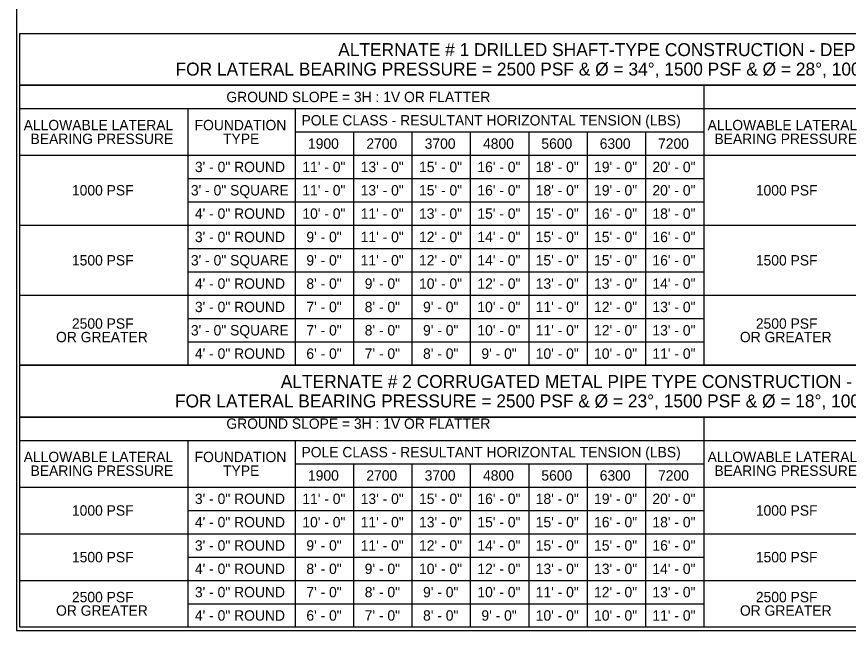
# Model space of a CAD drawing. Extents: x 99862 to 103151, y 100000 to 102076.
# Drawn here: x 99862 to 101145, y 100000 to 100946 of the extents above; entities that cross this region are included whole.
import ezdxf

# ---------------------------------------------------------------- set-up
doc = ezdxf.new("R2010")
doc.units = 0
for name, color, linetype in [('Level 1', 7, 'Continuous'), ('Level 20', 7, 'Continuous'), ('Level 40', 7, 'Continuous'), ('Level 60', 7, 'Continuous')]:
    doc.layers.add(name, color=color, linetype=linetype)

msp = doc.modelspace()

# ---------------------------------------------------------------- linework, layer by layer
at = {"layer": 'Level 1'}
msp.add_lwpolyline([(99862, 99999.5), (103151, 99999.5), (103151, 102075.5), (99862, 102075.5)], close=True, dxfattribs=at)
at = {"layer": 'Level 40'}
for p, q in [((100921.8, 100840.5), (100921.8, 100408.5)), ((99867, 100804.5), (101987.9, 100804.5)), ((100126, 100804.5), (100126, 100408.5)), ((100291.8, 100804.5), (100291.8, 100408.5)), ((100291.8, 100768.5), (100921.8, 100768.5)), ((100381.8, 100768.5), (100381.8, 100408.5)), ((100471.8, 100768.5), (100471.8, 100408.5)), ((100561.8, 100768.5), (100561.8, 100408.5)), ((100651.8, 100768.5), (100651.8, 100408.5)), ((100741.8, 100768.5), (100741.8, 100408.5)), ((100831.8, 100768.5), (100831.8, 100408.5)), ((99867, 100732.5), (101987.9, 100732.5)), ((100126, 100696.5), (100921.8, 100696.5)), ((100126, 100660.5), (100921.8, 100660.5)), ((99867, 100624.5), (101987.9, 100624.5)), ((100126, 100588.5), (100921.8, 100588.5)), ((100126, 100552.5), (100921.8, 100552.5)), ((99867, 100516.5), (101987.9, 100516.5)), ((100126, 100480.5), (100921.8, 100480.5)), ((100126, 100444.5), (100921.8, 100444.5)), ((100921.8, 100328.5), (100921.8, 100004.5)), ((99867, 100292.5), (101987.9, 100292.5)), ((100126, 100292.5), (100126, 100004.5)), ((100291.8, 100292.5), (100291.8, 100004.5)), ((100291.8, 100256.5), (100921.8, 100256.5)), ((100381.8, 100256.5), (100381.8, 100004.5)), ((100471.8, 100256.5), (100471.8, 100004.5)), ((100561.8, 100256.5), (100561.8, 100004.5)), ((100651.8, 100256.5), (100651.8, 100004.5)), ((100741.8, 100256.5), (100741.8, 100004.5)), ((100831.8, 100256.5), (100831.8, 100004.5)), ((99867, 100220.5), (101987.9, 100220.5)), ((100126, 100184.5), (100921.8, 100184.5)), ((99867, 100148.5), (101987.9, 100148.5)), ((100126, 100112.5), (100921.8, 100112.5)), ((99867, 100076.5), (101987.9, 100076.5)), ((100126, 100040.5), (100921.8, 100040.5))]:
    msp.add_line(p, q, dxfattribs=at)
for points in [[(99867, 100920.5), (101987.9, 100920.5), (101987.9, 100840.5), (99867, 100840.5)], [(99867, 100840.5), (101987.9, 100840.5), (101987.9, 100408.5), (99867, 100408.5)], [(99867, 100408.5), (101987.9, 100408.5), (101987.9, 100328.5), (99867, 100328.5)], [(99867, 100328.5), (101987.9, 100328.5), (101987.9, 100004.5), (99867, 100004.5)]]:
    msp.add_lwpolyline(points, close=True, dxfattribs=at)
at = {"layer": 'Level 60'}
msp.add_line((99862, 99999.5), (99862, 99999.5), dxfattribs=at)
msp.add_line((99862, 99999.5), (99862, 99999.5), dxfattribs=at)
msp.add_line((99862, 99999.5), (99862, 99999.5), dxfattribs=at)

# ---------------------------------------------------------------- texts
at = {"layer": 'Level 20'}
for s, height, p in [('ALTERNATE # 1 DRILLED SHAFT-TYPE CONSTRUCTION - DEPTH "D"', 20, (100358, 100885.5)), ('FOR LATERAL BEARING PRESSURE = 2500 PSF & Ø = 34°, 1500 PSF & Ø = 28°, 1000 PSF & Ø = 26°', 20, (100107.1, 100855.5)), ('GROUND SLOPE = 3H : 1V OR FLATTER', 16, (100185.5, 100814.5)), ('ALLOWABLE LATERAL', 16, (99872.9, 100771.1)), ('FOUNDATION', 16, (100136.5, 100771.1)), ('POLE CLASS - RESULTANT HORIZONTAL TENSION (LBS)', 16, (100301.4, 100778.5)), ('ALLOWABLE LATERAL', 16, (100927.8, 100771.1)), ('BEARING PRESSURE', 16, (99883.5, 100749.9)), ('TYPE', 16, (100180.4, 100749.9)), ('BEARING PRESSURE', 16, (100938.3, 100749.9)), ('1900', 16, (100311.4, 100742.5)), ('2700', 16, (100401.4, 100742.5)), ('3700', 16, (100491.4, 100742.5)), ('4800', 16, (100581.4, 100742.5)), ('5600', 16, (100671.4, 100742.5)), ('6300', 16, (100761.4, 100742.5)), ('7200', 16, (100851.4, 100742.5)), ('3\' - 0" ROUND', 16, (100137, 100706.5)), ('11\' - 0"', 16, (100302.7, 100706.5)), ('13\' - 0"', 16, (100392.7, 100706.5)), ('15\' - 0"', 16, (100482.7, 100706.5)), ('16\' - 0"', 16, (100572.7, 100706.5)), ('18\' - 0"', 16, (100662.7, 100706.5)), ('19\' - 0"', 16, (100752.7, 100706.5)), ('20\' - 0"', 16, (100842.7, 100706.5)), ('1000 PSF', 16, (99947.3, 100670.5)), ('3\' - 0" SQUARE', 16, (100130.8, 100670.5)), ('11\' - 0"', 16, (100302.7, 100670.5)), ('13\' - 0"', 16, (100392.7, 100670.5)), ('15\' - 0"', 16, (100482.7, 100670.5)), ('16\' - 0"', 16, (100572.7, 100670.5)), ('18\' - 0"', 16, (100662.7, 100670.5)), ('19\' - 0"', 16, (100752.7, 100670.5)), ('20\' - 0"', 16, (100842.7, 100670.5)), ('1000 PSF', 16, (101002.2, 100670.5)), ('4\' - 0" ROUND', 16, (100137, 100634.5)), ('10\' - 0"', 16, (100302.7, 100634.5)), ('11\' - 0"', 16, (100392.7, 100634.5)), ('13\' - 0"', 16, (100482.7, 100634.5)), ('15\' - 0"', 16, (100572.7, 100634.5)), ('15\' - 0"', 16, (100662.7, 100634.5)), ('16\' - 0"', 16, (100752.7, 100634.5)), ('18\' - 0"', 16, (100842.7, 100634.5)), ('3\' - 0" ROUND', 16, (100137, 100598.5)), ('9\' - 0"', 16, (100308.9, 100598.5)), ('11\' - 0"', 16, (100392.7, 100598.5)), ('12\' - 0"', 16, (100482.7, 100598.5)), ('14\' - 0"', 16, (100572.7, 100598.5)), ('15\' - 0"', 16, (100662.7, 100598.5)), ('15\' - 0"', 16, (100752.7, 100598.5)), ('16\' - 0"', 16, (100842.7, 100598.5)), ('1500 PSF', 16, (99947.3, 100562.5)), ('3\' - 0" SQUARE', 16, (100130.8, 100562.5)), ('9\' - 0"', 16, (100308.9, 100562.5)), ('11\' - 0"', 16, (100392.7, 100562.5)), ('12\' - 0"', 16, (100482.7, 100562.5)), ('14\' - 0"', 16, (100572.7, 100562.5)), ('15\' - 0"', 16, (100662.7, 100562.5)), ('15\' - 0"', 16, (100752.7, 100562.5)), ('16\' - 0"', 16, (100842.7, 100562.5)), ('1500 PSF', 16, (101002.2, 100562.5)), ('4\' - 0" ROUND', 16, (100137, 100526.5)), ('8\' - 0"', 16, (100308.9, 100526.5)), ('9\' - 0"', 16, (100398.9, 100526.5)), ('10\' - 0"', 16, (100482.7, 100526.5)), ('12\' - 0"', 16, (100572.7, 100526.5)), ('13\' - 0"', 16, (100662.7, 100526.5)), ('13\' - 0"', 16, (100752.7, 100526.5)), ('14\' - 0"', 16, (100842.7, 100526.5)), ('3\' - 0" ROUND', 16, (100137, 100490.5)), ('7\' - 0"', 16, (100308.9, 100490.5)), ('8\' - 0"', 16, (100398.9, 100490.5)), ('9\' - 0"', 16, (100488.9, 100490.5)), ('10\' - 0"', 16, (100572.7, 100490.5)), ('11\' - 0"', 16, (100662.7, 100490.5)), ('12\' - 0"', 16, (100752.7, 100490.5)), ('13\' - 0"', 16, (100842.7, 100490.5)), ('2500 PSF', 16, (99947.3, 100464.9)), ('2500 PSF', 16, (101002.2, 100464.9)), ('3\' - 0" SQUARE', 16, (100130.8, 100454.5)), ('7\' - 0"', 16, (100308.9, 100454.5)), ('8\' - 0"', 16, (100398.9, 100454.5)), ('9\' - 0"', 16, (100488.9, 100454.5)), ('10\' - 0"', 16, (100572.7, 100454.5)), ('11\' - 0"', 16, (100662.7, 100454.5)), ('12\' - 0"', 16, (100752.7, 100454.5)), ('13\' - 0"', 16, (100842.7, 100454.5)), ('OR GREATER', 16, (99922.8, 100444.1)), ('OR GREATER', 16, (100977.6, 100444.1)), ('4\' - 0" ROUND', 16, (100137, 100418.5)), ('6\' - 0"', 16, (100308.9, 100418.5)), ('7\' - 0"', 16, (100398.9, 100418.5)), ('8\' - 0"', 16, (100488.9, 100418.5)), ('9\' - 0"', 16, (100578.9, 100418.5)), ('10\' - 0"', 16, (100662.7, 100418.5)), ('10\' - 0"', 16, (100752.7, 100418.5)), ('11\' - 0"', 16, (100842.7, 100418.5)), ('ALTERNATE # 2 CORRUGATED METAL PIPE TYPE CONSTRUCTION - DEPTH "D"', 20, (100269.5, 100373.5)), ('FOR LATERAL BEARING PRESSURE = 2500 PSF & Ø = 23°, 1500 PSF & Ø = 18°, 1000 PSF & Ø = 17°', 20, (100106.2, 100343.5)), ('GROUND SLOPE = 3H : 1V OR FLATTER', 16, (100185.5, 100310.5)), ('ALLOWABLE LATERAL', 16, (99872.9, 100259.1)), ('FOUNDATION', 16, (100136.5, 100259.1)), ('POLE CLASS - RESULTANT HORIZONTAL TENSION (LBS)', 16, (100301.4, 100266.5)), ('ALLOWABLE LATERAL', 16, (100927.8, 100259.1)), ('BEARING PRESSURE', 16, (99883.5, 100237.9)), ('TYPE', 16, (100180.4, 100237.9)), ('1900', 16, (100311.4, 100230.5)), ('2700', 16, (100401.4, 100230.5)), ('3700', 16, (100491.4, 100230.5)), ('4800', 16, (100581.4, 100230.5)), ('5600', 16, (100671.4, 100230.5)), ('6300', 16, (100761.4, 100230.5)), ('7200', 16, (100851.4, 100230.5)), ('BEARING PRESSURE', 16, (100938.3, 100237.9)), ('3\' - 0" ROUND', 16, (100137, 100194.5)), ('11\' - 0"', 16, (100302.7, 100194.5)), ('13\' - 0"', 16, (100392.7, 100194.5)), ('15\' - 0"', 16, (100482.7, 100194.5)), ('16\' - 0"', 16, (100572.7, 100194.5)), ('18\' - 0"', 16, (100662.7, 100194.5)), ('19\' - 0"', 16, (100752.7, 100194.5)), ('20\' - 0"', 16, (100842.7, 100194.5)), ('1000 PSF', 16, (99947.3, 100176.5)), ('1000 PSF', 16, (101002.2, 100176.5)), ('4\' - 0" ROUND', 16, (100137, 100158.5)), ('10\' - 0"', 16, (100302.7, 100158.5)), ('11\' - 0"', 16, (100392.7, 100158.5)), ('13\' - 0"', 16, (100482.7, 100158.5)), ('15\' - 0"', 16, (100572.7, 100158.5)), ('15\' - 0"', 16, (100662.7, 100158.5)), ('16\' - 0"', 16, (100752.7, 100158.5)), ('18\' - 0"', 16, (100842.7, 100158.5)), ('3\' - 0" ROUND', 16, (100137, 100122.5)), ('9\' - 0"', 16, (100308.9, 100122.5)), ('11\' - 0"', 16, (100392.7, 100122.5)), ('12\' - 0"', 16, (100482.7, 100122.5)), ('14\' - 0"', 16, (100572.7, 100122.5)), ('15\' - 0"', 16, (100662.7, 100122.5)), ('15\' - 0"', 16, (100752.7, 100122.5)), ('16\' - 0"', 16, (100842.7, 100122.5)), ('1500 PSF', 16, (99947.3, 100104.5)), ('1500 PSF', 16, (101002.2, 100104.5)), ('4\' - 0" ROUND', 16, (100137, 100086.5)), ('8\' - 0"', 16, (100308.9, 100086.5)), ('9\' - 0"', 16, (100398.9, 100086.5)), ('10\' - 0"', 16, (100482.7, 100086.5)), ('12\' - 0"', 16, (100572.7, 100086.5)), ('13\' - 0"', 16, (100662.7, 100086.5)), ('13\' - 0"', 16, (100752.7, 100086.5)), ('14\' - 0"', 16, (100842.7, 100086.5)), ('3\' - 0" ROUND', 16, (100137, 100050.5)), ('7\' - 0"', 16, (100308.9, 100050.5)), ('8\' - 0"', 16, (100398.9, 100050.5)), ('9\' - 0"', 16, (100488.9, 100050.5)), ('10\' - 0"', 16, (100572.7, 100050.5)), ('11\' - 0"', 16, (100662.7, 100050.5)), ('12\' - 0"', 16, (100752.7, 100050.5)), ('13\' - 0"', 16, (100842.7, 100050.5)), ('2500 PSF', 16, (99947.3, 100042.9)), ('2500 PSF', 16, (101002.2, 100042.9)), ('OR GREATER', 16, (99922.8, 100022.1)), ('4\' - 0" ROUND', 16, (100137, 100014.5)), ('6\' - 0"', 16, (100308.9, 100014.5)), ('7\' - 0"', 16, (100398.9, 100014.5)), ('8\' - 0"', 16, (100488.9, 100014.5)), ('9\' - 0"', 16, (100578.9, 100014.5)), ('10\' - 0"', 16, (100662.7, 100014.5)), ('10\' - 0"', 16, (100752.7, 100014.5)), ('11\' - 0"', 16, (100842.7, 100014.5)), ('OR GREATER', 16, (100977.6, 100022.1))]:
    msp.add_text(s, height=height, dxfattribs=at).set_placement(p)

doc.saveas('drawing.dxf')
